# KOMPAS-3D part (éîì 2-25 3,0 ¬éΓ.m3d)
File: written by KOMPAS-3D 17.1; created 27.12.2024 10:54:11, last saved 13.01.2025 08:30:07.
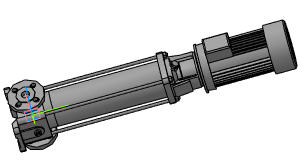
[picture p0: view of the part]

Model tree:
1. Операция без истории:4  (labels: ВМН 2-25 3,0 кВт)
